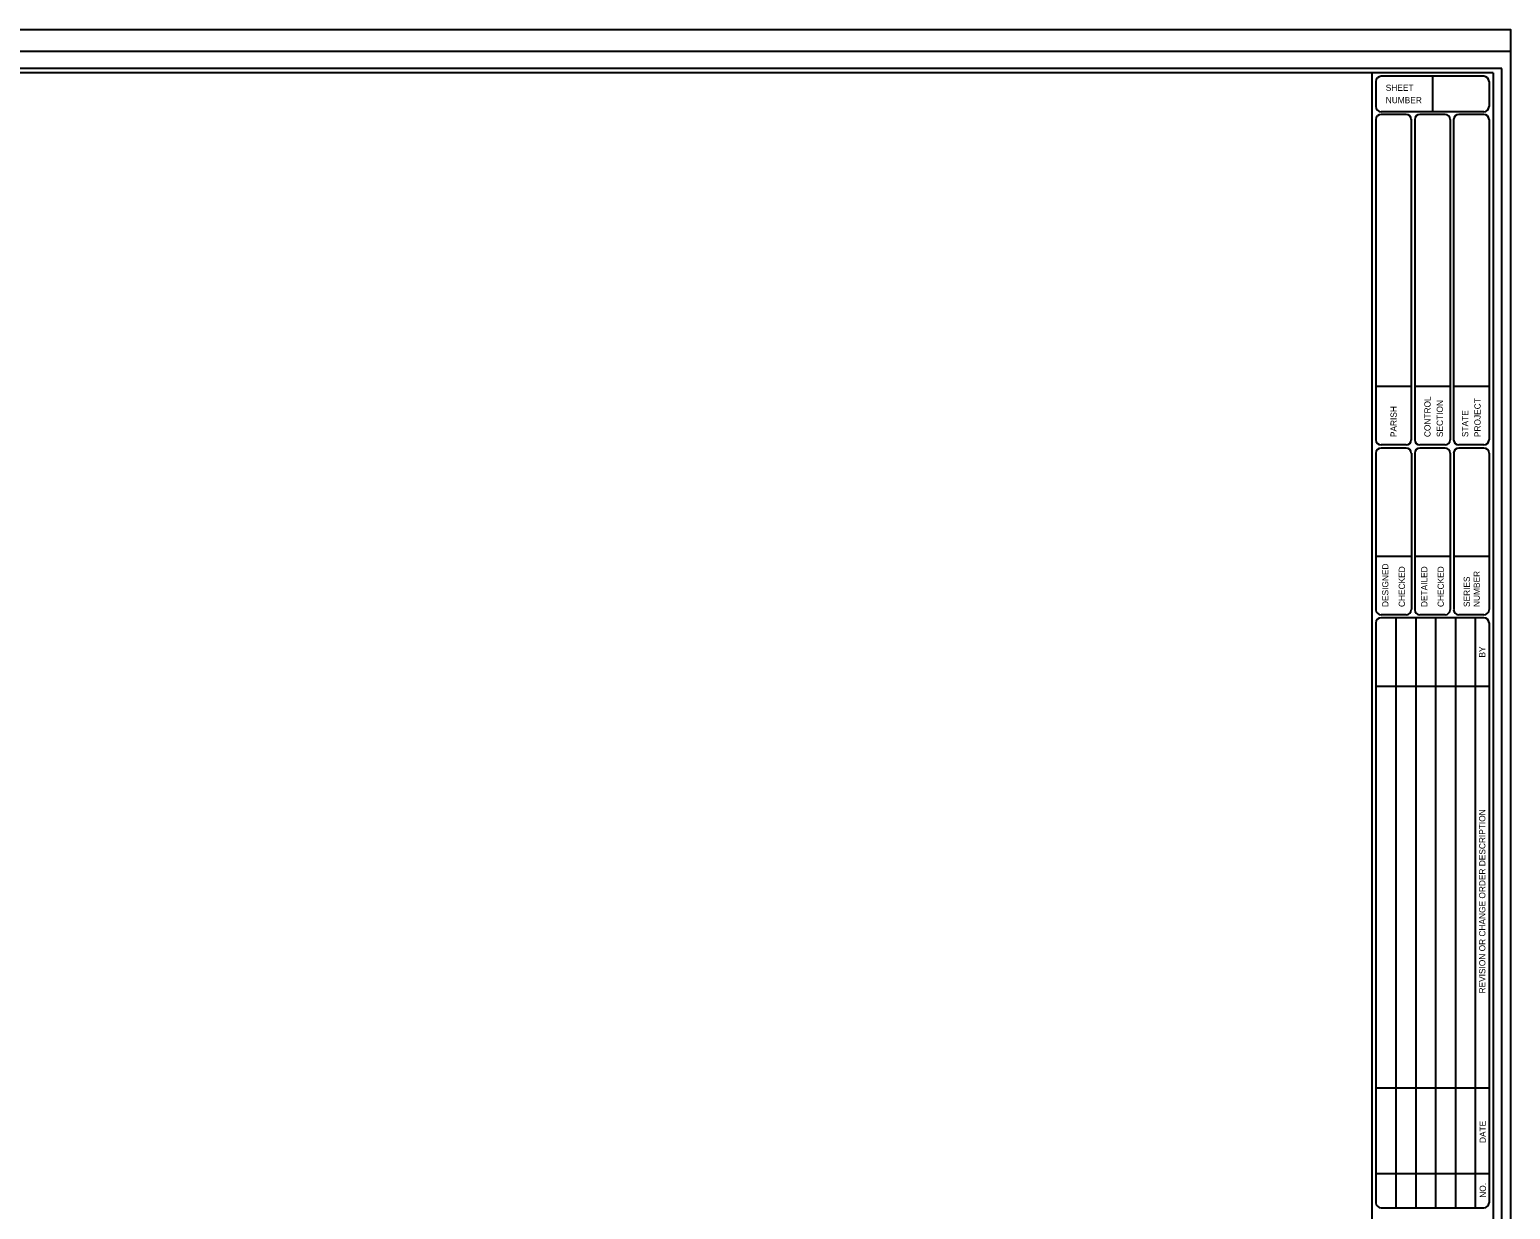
# Model space of a CAD drawing. Extents: x -2.5 to 31.7, y -0.7 to 21.7.
# Drawn here: x 14.59 to 31.7, y 7.86 to 21.5 of the extents above; entities that cross this region are included whole.
import ezdxf

# ---------------------------------------------------------------- set-up
doc = ezdxf.new("R2010")
doc.units = 0
for name, color, linetype in [('Plot Border', 7, 'Continuous'), ('Plot Border 2', 7, 'Continuous'), ('Sheet Border', 7, 'Continuous')]:
    doc.layers.add(name, color=color, linetype=linetype)

msp = doc.modelspace()

# ---------------------------------------------------------------- linework, layer by layer
at = {"layer": 'Plot Border'}
for points in [[(-2.3, 21.5), (31.7, 21.5), (31.7, -0.5), (-2.3, -0.5)], [(31.6, 21.05), (-1.4, 21.05), (-1.4, -0.05), (31.6, -0.05)]]:
    msp.add_lwpolyline(points, close=True, dxfattribs=at)
at = {"layer": 'Plot Border 2'}
msp.add_lwpolyline([(-2.3, 21.25), (31.7, 21.25), (31.7, -0.25), (-2.3, -0.25)], close=True, dxfattribs=at)
at = {"layer": 'Sheet Border'}
for p, q in [((31.5, 21), (0, 21)), ((30.1, 21), (30.1, 0)), ((30.146, 20.901), (30.146, 20.611)), ((31.394, 20.96), (30.206, 20.96)), ((30.8, 20.96), (30.8, 20.551)), ((31.454, 20.901), (31.454, 20.611)), ((31.5, 21), (31.5, 0)), ((31.394, 20.551), (30.206, 20.551)), ((30.146, 20.464), (30.146, 16.754)), ((30.496, 20.52), (30.206, 20.52)), ((30.555, 20.465), (30.555, 16.754)), ((30.595, 20.46), (30.595, 16.759)), ((30.945, 20.52), (30.654, 20.52)), ((31.005, 20.461), (31.005, 16.758)), ((31.044, 20.46), (31.044, 16.759)), ((31.394, 20.52), (31.104, 20.52)), ((31.454, 20.46), (31.454, 16.759)), ((30.555, 17.373), (30.146, 17.373)), ((31.005, 17.373), (30.595, 17.373)), ((31.454, 17.373), (31.044, 17.373)), ((30.146, 16.608), (30.146, 14.796)), ((30.496, 16.699), (30.206, 16.699)), ((30.496, 16.663), (30.206, 16.663)), ((30.556, 16.603), (30.556, 14.796)), ((30.595, 16.608), (30.595, 14.796)), ((30.945, 16.699), (30.654, 16.699)), ((30.946, 16.663), (30.655, 16.663)), ((31.005, 16.603), (31.005, 14.796)), ((31.045, 16.608), (31.045, 14.796)), ((31.394, 16.699), (31.104, 16.699)), ((31.395, 16.663), (31.104, 16.663)), ((31.454, 16.603), (31.454, 14.796)), ((30.555, 15.41), (30.146, 15.41)), ((31.005, 15.41), (30.595, 15.41)), ((31.454, 15.41), (31.044, 15.41)), ((30.496, 14.736), (30.206, 14.736)), ((30.946, 14.736), (30.655, 14.736)), ((31.395, 14.736), (31.104, 14.736)), ((30.146, 14.643), (30.146, 7.941)), ((31.394, 14.701), (30.206, 14.701)), ((30.376, 14.701), (30.376, 7.882)), ((30.606, 14.701), (30.606, 7.882)), ((30.836, 14.701), (30.836, 7.882)), ((31.065, 14.701), (31.065, 7.882)), ((31.295, 14.701), (31.295, 7.882)), ((31.454, 14.643), (31.454, 7.941)), ((31.454, 13.909), (30.146, 13.909)), ((30.146, 9.269), (31.454, 9.269)), ((30.146, 8.278), (31.454, 8.278)), ((30.206, 7.882), (31.394, 7.882))]:
    msp.add_line(p, q, dxfattribs=at)
for centre, start, end in [((30.206, 20.901), 90, 180), ((31.394, 20.901), 0, 90), ((30.206, 20.61), 180, 270), ((31.394, 20.61), 270, 0), ((30.206, 20.46), 90, 180), ((30.496, 20.46), 0, 90), ((30.655, 20.46), 90, 180), ((30.945, 20.46), 0, 90), ((31.104, 20.46), 90, 180), ((31.394, 20.46), 0, 90), ((30.206, 16.759), 180, 270), ((30.206, 16.604), 90, 180), ((30.496, 16.759), 270, 0), ((30.496, 16.604), 0, 90), ((30.655, 16.759), 180, 270), ((30.655, 16.604), 90, 180), ((30.945, 16.759), 270, 0), ((30.945, 16.604), 0, 90), ((31.104, 16.759), 180, 270), ((31.104, 16.604), 90, 180), ((31.394, 16.759), 270, 0), ((31.395, 16.604), 0, 90), ((30.206, 14.795), 180, 270), ((30.496, 14.795), 270, 0), ((30.655, 14.795), 180, 270), ((30.945, 14.795), 270, 0), ((31.104, 14.795), 180, 270), ((31.395, 14.795), 270, 0), ((30.206, 14.643), 90, 180), ((31.394, 14.643), 0, 90), ((30.206, 7.941), 180, 270), ((31.394, 7.941), 270, 0)]:
    msp.add_arc(centre, 0.0594, start, end, dxfattribs=at)

# ---------------------------------------------------------------- texts
for s, p in [('SHEET', (30.26, 20.792)), ('NUMBER', (30.26, 20.649))]:
    msp.add_text(s, height=0.072, dxfattribs=at).set_placement(p)
for s, p in [('PARISH', (30.387, 16.79)), ('CONTROL', (30.778, 16.79)), ('SECTION', (30.921, 16.79)), ('PROJECT', (31.356, 16.79)), ('STATE', (31.213, 16.79)), ('DESIGNED', (30.291, 14.826)), ('CHECKED', (30.482, 14.826)), ('DETAILED', (30.741, 14.826)), ('CHECKED', (30.931, 14.826)), ('NUMBER', (31.347, 14.826)), ('SERIES', (31.232, 14.826)), ('BY', (31.411, 14.242)), ('REVISION OR CHANGE ORDER DESCRIPTION', (31.411, 10.359)), ('DATE', (31.416, 8.631)), ('NO.', (31.417, 7.998))]:
    msp.add_text(s, height=0.072, rotation=90, dxfattribs=at).set_placement(p)

doc.saveas('drawing.dxf')
